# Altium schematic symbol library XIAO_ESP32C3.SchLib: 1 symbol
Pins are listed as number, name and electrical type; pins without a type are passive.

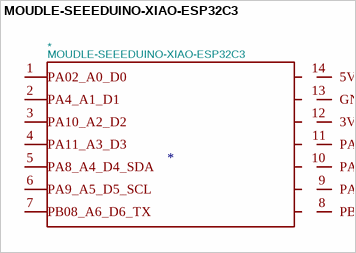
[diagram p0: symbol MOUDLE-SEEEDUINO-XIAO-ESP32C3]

## MOUDLE-SEEEDUINO-XIAO-ESP32C3
designator *  value MOUDLE-SEEEDUINO-XIAO-ESP32C3
footprint MOUDLE14P-SMD-2.54-21X17.8MM
pins: 1 PA02_A0_D0, 2 PA4_A1_D1, 3 PA10_A2_D2, 4 PA11_A3_D3, 5 PA8_A4_D4_SDA, 6 PA9_A5_D5_SCL, 7 PB08_A6_D6_TX, 8 PB09_A7_D7_RX, 9 PA7_A8_D8_SCK, 10 PA5_A9_D9_MISO, 11 PA6_A10_D10_MOSI, 12 3V3, 13 GND, 14 5V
